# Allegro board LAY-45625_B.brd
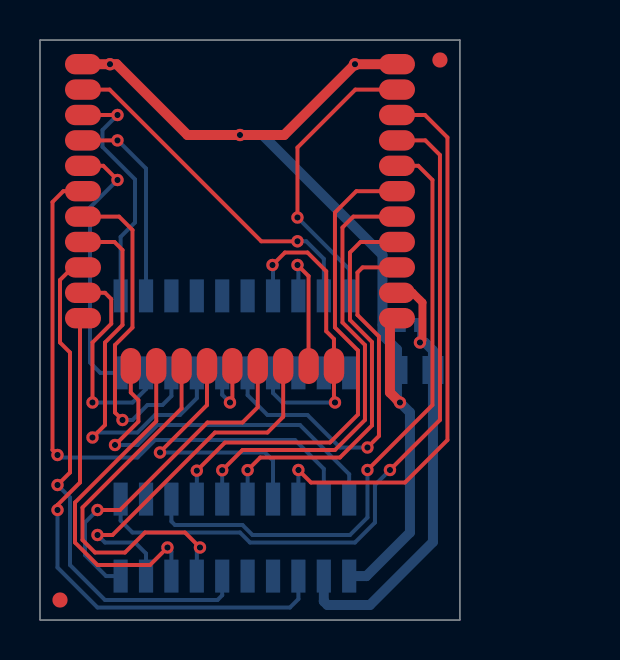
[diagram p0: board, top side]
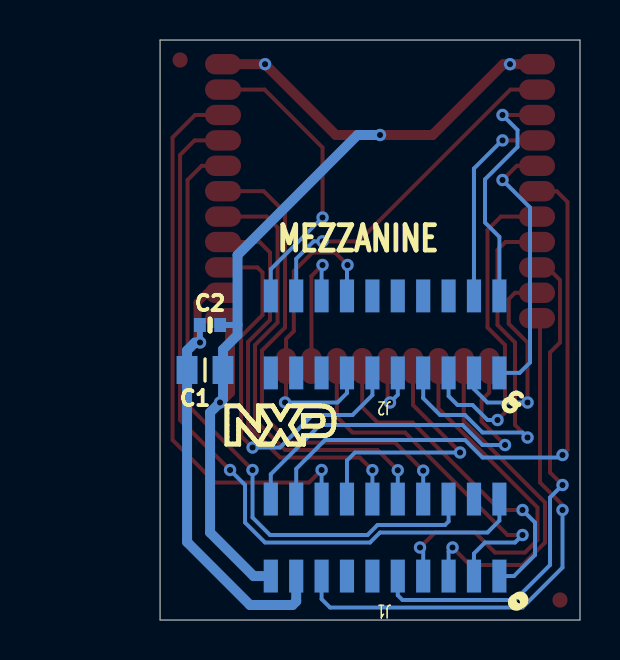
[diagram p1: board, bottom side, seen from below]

Outline 21 x 29 mm; copper layers: TOP, BOTTOM. Coordinates in mm from the lower left corner of the outline.
Outline path: 0,29 21,29 21,0 0,0 0,29

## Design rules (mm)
net group PH_SP_ALIM: nets VDD
net group PH_SP_DEFAULT: nets ANT_SEL LA LB LNA_BYPASS PIO_0/SPI1_SCK PIO_1/SPI1_MISO PIO_2/SPI1_MOSI PIO_3/SPI1_SSELN0 PIO_4/PWM4-PU PIO_5/ISP_ENTRY PIO_6/PWM6-PD PIO_7/PWM7-PD PIO_8/USART0_TXD PIO_9/USART0_RXD PIO_10/I2C0_SCL PIO_11/I2C0_SDA PIO_12/SWCLK PIO_13/SWDIO PIO_14/ADC0 PIO_15/ADC1 PIO_16/SPIFI_CSN PIO_17/SPIFI_IO3 PIO_18/SPIFI_CLK PIO_19/SPIFI_IO0 PIO_20/SPIFI_IO2 PIO_21_SPIFI_IO1 RSTN
net group PH_SP_MASSE: nets GND

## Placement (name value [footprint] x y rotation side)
1  BUBBLE01_CI  [BUBBLE_DIAM8]  27 7.56 0 top
C1  NC_22uF  [C0805]  18.75 12.5 180 bottom
C2  NC_100nF  [C0402]  18.5 14.75 180 bottom
FID1  NC  [FID1]  20 28 0 top
FID2  NC  [FID1]  1 1 0 top
J1  -  [M50-3121045]  9.75 4.12 0 bottom
J2  -  [M50-3121045]  9.75 14.28 0 bottom
LY1  NC  [SMD_LYRE_31PTS_MEZZA_JN518X]  2 25.25 0 top
NOREF  -  []  130.5 -19.5 0 top
NOREF#2  -  []  0 0 90 top
NOREF#3  -  []  0 0 0 top
NOREF#4  -  []  -74 -87 0 top
NOREF#5  -  []  -77.65 35.55 0 top
NOREF#6  -  []  15 9.75 180 bottom

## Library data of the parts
1 = BUBBLE: alternate symbols: (BUBBLE_DIAM4)
C1 = CAPA: alternate symbols: (0805C); tolerance: 20%
C2 = CAPA: User Part Number: BCNNUMBER; Tolerance: 5%; alternate symbols: (0402C); tolerance: 5%
FID1 FID2 = MIRE
J1 J2 = CON20AP
LY1 = LYRE_MODJN518x_31PTS

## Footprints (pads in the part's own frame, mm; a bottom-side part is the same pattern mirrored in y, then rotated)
BUBBLE_DIAM8
  round 0 smd: 1(0,0)
C0402
  rect 0.6x0.7 smd: 1(-0.508,0) 2(0.508,0)
C0805
  rect 1.05x1.4 smd: 1(-0.9,0) 2(0.9,0)
FID1
  round 0.76 smd: 1(0,0)
M50-3121045
  rect 0.71x1.65 smd: 1(-5.715,1.925) 2(-5.715,-1.925) 3(-4.445,1.925) 4(-4.445,-1.925) 5(-3.175,1.925) 6(-3.175,-1.925) 7(-1.905,1.925) 8(-1.905,-1.925) 9(-0.635,1.925) 10(-0.635,-1.925) 11(0.635,1.925) 12(0.635,-1.925) 13(1.905,1.925) 14(1.905,-1.925) 15(3.175,1.925) 16(3.175,-1.925) 17(4.445,1.925) 18(4.445,-1.925) 19(5.715,1.925) 20(5.715,-1.925)
SMD_LYRE_31PTS_MEZZA_JN518X
  oval 1.8x1.02 smd: 1(0,2.54) 2(0,1.27) 3(0,0) 4(0,-1.27) 5(0,-2.54) 6(0,-3.81) 7(0,-5.08) 8(0,-6.35) 9(0,-7.62) 10(0,-8.89) 11(0,-10.16) 21(16,-10.16) 22(16,-8.89) 23(16,-7.62) 24(16,-6.35) 25(16,-5.08) 26(16,-3.81) 27(16,-2.54) 28(16,-1.27) 29(16,0) 30(16,1.27) 31(16,2.54)
  oval 1.02x1.8 smd: 12(2.54,-12.7) 13(3.81,-12.7) 14(5.08,-12.7) 15(6.35,-12.7) 16(7.62,-12.7) 17(8.89,-12.7) 18(10.16,-12.7) 19(11.43,-12.7) 20(12.7,-12.7)

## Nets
GND: C1.2 C2.2 J1.19 LY1.1 LY1.21 LY1.31
VDD: C1.1 C2.1 J1.17 LY1.22(VDD)
ANT_SEL: J2.18 LY1.2
LA: J2.4 LY1.4
LB: J2.2 LY1.3
LNA_BYPASS: J2.20 LY1.30
PIO_0/SPI1_SCK: J2.1 LY1.5
PIO_1/SPI1_MISO: J1.18 LY1.6
PIO_2/SPI1_MOSI: J2.5 LY1.7
PIO_3/SPI1_SSELN0: J2.7 LY1.8
PIO_4/PWM4-PU: J1.9 LY1.9
PIO_5/ISP_ENTRY: J2.3 LY1.10
PIO_6/PWM6-PD: J1.15 LY1.11
PIO_7/PWM7-PD: J1.20 LY1.12
PIO_8/USART0_TXD: J1.5 LY1.13
PIO_9/USART0_RXD: J1.7 LY1.14
PIO_10/I2C0_SCL: J1.14 LY1.15
PIO_11/I2C0_SDA: J2.9 LY1.16
PIO_12/SWCLK: J1.1 LY1.17
PIO_13/SWDIO: J1.3 LY1.18
PIO_14/ADC0: J2.16 LY1.19
PIO_15/ADC1: J2.13 J2.14 LY1.20
PIO_16/SPIFI_CSN: J2.11 LY1.23
PIO_17/SPIFI_IO3: J1.12 LY1.24
PIO_18/SPIFI_CLK: J1.10 LY1.25
PIO_19/SPIFI_IO0: J1.8 LY1.26
PIO_20/SPIFI_IO2: J1.6 LY1.27
PIO_21_SPIFI_IO1: J1.2 LY1.28
RSTN: J1.16 LY1.29

Pads without a net: 1 1; FID1 1; FID2 1; J1 4 11 13; J2 6 8 10 12 15 17 19

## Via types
v1: diameter 0.62, hole 0.31, TOP to BOTTOM, 33 vias

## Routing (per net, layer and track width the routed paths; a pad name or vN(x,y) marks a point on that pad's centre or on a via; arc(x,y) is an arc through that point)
GND: length 52.5
  TOP w0.5: v1(18,10.88) 17.5,11.38 17.5,14.74 17.85,15.09 LY1.21 ; LY1.1 v1(3.5,27.79) 3.83,27.79 7.38,24.25 v1(10,24.25) 12.21,24.25 v1(15.75,27.79) LY1.31
  BOTTOM w0.3: 17.12,14.75 C2.2
  BOTTOM w0.5: v1(10,24.25) 11.12,24.25 17.12,18.25 17.12,14.25 17.85,13.53 C1.2 17.85,11.03 v1(18,10.88) 18.5,10.38 18.5,4.38 16.32,2.2 J1.19
VDD: length 22.7
  TOP w0.4: v1(19,13.88) 19.12,14 19.12,15.88 18.64,16.36 LY1.22
  BOTTOM w0.3: C2.1 19.01,13.88 v1(19,13.88)
  BOTTOM w0.5: v1(19,13.88) 19.25,13.88 19.65,13.47 C1.1 19.65,3.9 16.5,0.75 14.38,0.75 14.19,0.93 J1.17
ANT_SEL: length 17.5
  TOP w0.2: v1(12.88,18.93) 11.06,18.93 3.48,26.52 LY1.2
  BOTTOM w0.2: v1(12.88,18.93) 13.31,18.93 14.19,18.06 J2.18
LA: length 10.3
  TOP w0.2: LY1.4 v1(3.88,23.98)
  BOTTOM w0.2: J2.4 5.3,22.57 3.9,23.98 v1(3.88,23.98)
LB: length 12.2
  TOP w0.2: LY1.3 v1(3.88,25.25)
  BOTTOM w0.2: v1(3.88,25.25) 3.12,24.5 3.12,23.66 4.75,22.03 4.75,19.88 4.03,19.16 J2.2
LNA_BYPASS: length 14.8
  TOP w0.2: LY1.30 15.77,26.52 12.88,23.62 v1(12.88,20.12)
  BOTTOM w0.2: J2.20 15.46,17.54 v1(12.88,20.12)
PIO_0/SPI1_SCK: length 13.6
  TOP w0.2: v1(3.88,22) 3.17,22.71 LY1.5
  BOTTOM w0.2: v1(3.88,22) 2.5,20.62 2.5,12.88 3.02,12.36 J2.1
PIO_1/SPI1_MISO: length 30.2
  TOP w0.2: v1(0.88,8.25) 0.62,8.5 0.62,20.9 1.17,21.44 LY1.6
  BOTTOM w0.2: v1(0.88,8.25) 1,8.12 4.88,8.12 5.75,9 12.75,9 14.19,7.56 J1.18
PIO_2/SPI1_MOSI: length 17
  TOP w0.2: v1(4.12,10) 3.75,10.38 3.75,13.75 4.62,14.62 4.62,19.5 3.96,20.17 LY1.7
  BOTTOM w0.2: v1(4.12,10) 4.62,10 5.38,10.75 6.12,10.75 6.57,11.2 J2.5
PIO_3/SPI1_SSELN0: length 19.6
  TOP w0.2: v1(2.62,9.12) 3.25,9.75 3.25,13.88 4.12,14.75 4.12,18.5 3.73,18.9 LY1.8
  BOTTOM w0.2: J2.7 7.84,11.09 7,10.25 5.75,10.25 4.88,9.38 2.88,9.38 v1(2.62,9.12)
PIO_4/PWM4-PU: length 25.6
  TOP w0.2: LY1.9 1.63,17.63 1,17 1,13.88 1.5,13.38 1.5,7.38 v1(0.88,6.75)
  BOTTOM w0.2: v1(0.88,6.75) 1.5,6.12 1.5,2.75 3.25,1 8.88,1 9.11,1.24 J1.9
PIO_5/ISP_ENTRY: length 11
  TOP w0.2: v1(2.62,10.88) 2.62,13.88 3.56,14.81 3.56,16.05 3.25,16.36 LY1.10
  BOTTOM w0.2: J2.3 5.3,11.55 4.63,10.88 v1(2.62,10.88)
PIO_6/PWM6-PD: length 27.1
  TOP w0.2: LY1.11 2,6.88 0.88,5.75 v1(0.88,5.5)
  BOTTOM w0.2: J1.15 12.92,1.05 12.5,0.62 2.88,0.62 0.88,2.62 v1(0.88,5.5)
PIO_7/PWM7-PD: length 18.8
  TOP w0.2: LY1.12 4.54,11.38 4.92,10.99 4.92,9.92 v1(3.75,8.75)
  BOTTOM w0.2: J1.20 15.46,7.29 13,9.75 5.88,9.75 4.88,8.75 v1(3.75,8.75)
PIO_8/USART0_TXD: length 17.3
  TOP w0.2: v1(6.38,3.62) 5.5,2.75 2.88,2.75 1.75,3.88 1.75,5.88 5.81,9.94 5.81,12.55 LY1.13
  BOTTOM w0.2: v1(6.38,3.62) 6.57,3.43 J1.5
PIO_9/USART0_RXD: length 19
  TOP w0.2: v1(8,3.62) 7.25,4.38 5.25,4.38 4.25,3.38 2.75,3.38 2.12,4 2.12,5.62 7.08,10.58 LY1.14
  BOTTOM w0.2: v1(8,3.62) 7.84,3.47 J1.7
PIO_10/I2C0_SCL: length 12.9
  TOP w0.2: v1(6,8.38) 6,8.39 8.35,10.74 LY1.15
  BOTTOM w0.2: J1.14 11.65,7.97 11.25,8.38 v1(6,8.38)
PIO_11/I2C0_SDA: length 3.4
  TOP w0.2: LY1.16 9.62,10.99 v1(9.5,10.88)
  BOTTOM w0.2: v1(9.5,10.88) 9.11,11.26 J2.9
PIO_12/SWCLK: length 16.8
  TOP w0.2: v1(2.88,5.5) 4,5.5 8.38,9.88 10.12,9.88 10.89,10.64 LY1.17
  BOTTOM w0.2: v1(2.88,5.5) 2.25,4.88 2.25,3.25 3.3,2.2 J1.1
PIO_13/SWDIO: length 18.1
  TOP w0.2: v1(2.88,4.25) 3.62,4.25 8.75,9.38 11.38,9.38 12.16,10.16 LY1.18
  BOTTOM w0.2: v1(2.88,4.25) 3.25,3.88 4.75,3.88 5.3,3.32 J1.3
PIO_14/ADC0: length 7
  TOP w0.2: v1(12.88,17.75) 13.43,17.2 LY1.19
  BOTTOM w0.2: J2.16 12.92,17.7 v1(12.88,17.75)
PIO_15/ADC1: length 15.9
  TOP w0.2: v1(14.75,10.88) 14.7,10.93 LY1.20 14.7,14.05 14.31,14.44 14.31,17.44 13.38,18.38 12.25,18.38 v1(11.62,17.75)
  BOTTOM w0.2: v1(11.62,17.75) 11.65,17.72 J2.14 ; v1(14.75,10.88) 12.12,10.88 11.65,11.35 J2.13
PIO_16/SPIFI_CSN: length 19.9
  TOP w0.2: LY1.23 16.13,17.63 15.88,17.38 15.88,15.25 16.95,14.18 16.95,9.2 v1(16.38,8.62)
  BOTTOM w0.2: J2.11 10.38,11.24 11.38,10.25 13.38,10.25 15,8.62 v1(16.38,8.62)
PIO_17/SPIFI_IO3: length 20.4
  TOP w0.2: LY1.24 16.02,18.9 15.5,18.38 15.5,15 16.6,13.9 16.6,9.72 15,8.12 11.01,8.12 v1(10.38,7.49)
  BOTTOM w0.2: J1.12 v1(10.38,7.49)
PIO_18/SPIFI_CLK: length 22.8
  TOP w0.2: v1(9.11,7.49) 10.12,8.5 14.75,8.5 16.25,10 16.25,13.75 15.12,14.88 15.12,19.62 15.67,20.17 LY1.25
  BOTTOM w0.2: J1.10 v1(9.11,7.49)
PIO_19/SPIFI_IO0: length 24.9
  TOP w0.2: LY1.26 15.81,21.44 14.75,20.38 14.75,14.62 15.9,13.47 15.9,10.28 14.5,8.88 9.25,8.88 v1(7.84,7.47)
  BOTTOM w0.2: J1.8 v1(7.84,7.47)
PIO_20/SPIFI_IO2: length 31.7
  TOP w0.2: v1(16.38,7.5) 19.62,10.75 19.62,22 18.91,22.71 LY1.27
  BOTTOM w0.2: J1.6 6.57,4.93 6.75,4.75 10.12,4.75 10.62,4.25 15.5,4.25 16.38,5.12 v1(16.38,7.5)
PIO_21_SPIFI_IO1: length 36.7
  TOP w0.2: LY1.28 19.27,23.98 20,23.25 20,10 v1(17.5,7.5)
  BOTTOM w0.2: v1(17.5,7.5) 16.75,6.75 16.75,4.88 15.75,3.88 10.5,3.88 10,4.38 4.62,4.38 4.03,4.97 J1.2
RSTN: length 28
  TOP w0.2: LY1.29 19.25,25.25 20.38,24.12 20.38,9 18.25,6.88 13.55,6.88 v1(12.92,7.5)
  BOTTOM w0.2: v1(12.92,7.5) J1.16

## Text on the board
Ref Des/Assembly Bottom: BOTTOM
Ref Des/Silkscreen Bottom: MEZZANINE
Ref Des/Assembly Top: TOP
MARQUAGE_COMMUN: B
User.6: PCB2410-2 OM15026-1 JN5179 MEZZANINE 06/10/2015 | MILLING 313 00
User.25: INT3 311 00 | LAYER 3
User.26: INT2 311 00 | LAYER 2
User.45: 1 | CN2 | CN1 | M2 | M1 | R10 | R15 | R14 | R12 | R13 | R11 | R9 | R7 | R2 | R8 | R5 | R3 | M5 | IC10 | IC11 | IC12 | D1 | IC7 | IC8 | IC9 | D2 | K | R16 | IC5 | IC1 | IC4 | IC3 | IC6 | IC2 | R17 | D3 | D13 | C1 | RG1 | D5 | R50 | R51 | R52 | R24 | C2 | D4 | R25 | IC17 | IC18 | IC19 | SP1 | D6 | C8 | C6 | IC13 | J4 | IC16 | C7 | ANT1 | TP4 | TP3 | JP2 | C14 | R36 | SW1 | TP2 | TP1 | IC15 | D9 | R40 | D8 | CN4 | CN3 | J2 | J1 | M3 | SP2 | R42 | SP4 | C10 | C15 | ST1 | SP5 | R43 | SP3 | SP6 | ST2 | C16 | SP7 | J5 | C13 | M6 | SP8 | JP4 | JP3 | SP10 | JP5 | SP9 | SW2 | SP11 | SP12 | M4 | JP6 | 2 | 3 | IC14 | J6 | R4 | R6 | C5 | C4 | C3 | R1 | R22 | R21 | R20 | R19 | R18 | R23 | J3 | R49 | C19 | R29 | R28 | R26 | R27 | R35 | R34 | R33 | R32 | R31 | R30 | R37 | D7 | R38 | C9 | FE1 | R39 | R41 | C17 | C11 | Y1 | C12 | R44 | R45 | D12 | D11 | D10 | C18 | R48 | R47 | R46 | JP1 | LAY-45625_B | PCB2445-1 | PCB2446-1 | PCB2447-1 | PCB2448-1 | OM15064-1 PCB2445-1 | OM15065-1 PCB2446-1 | OM15067-1 PCB2447-1 | OM15068-1 PCB2448-1 | BOARD ORIENTATION | All rights are reserved. Reproduction in | whole or in part is prohibited without | the written consent of the copyright owner | OM15064-1 | OM15065-1 | OM15067-1 | OM15068-1 | OM15077 | NXP Semiconductors | 6501 William Cannon Drive West | Austin, TX 78735-8598 | Date | Draw by | Verify | Modifications | SIZE | IND. | Date : 08-Nov-2019 | Draw by : ASCO-SR | Checked by: V.FILLATRE | Project : OM15077 | ASSEMBLY DRAWING TOP/BOTTOM | MEZZANINE - OM15077 | DRILLING/MILLING | Protection: SOLDERMASK(BLUE) | Finition : Ni/AU CHEMICAL | Material : ... | File. | TOP/BOTTOM | Marging : +/-0.1 | Manufact.level : 5 | Scale : 1/1 | Nbr of layers : 2 | Silkscreen(WHITE) | TOP   : NO | BOTTOM: YES | REV. | PL. | FR4,16/10mm | COLOR | JN5179 MEZZANINE 19/04/2016 | JN518X MEZZANINE | PCB2457-1.0_OM15077-1 | PCB2444-1.0 OM15063-1 | BLUE | FIGURE | DIAMETRE / HOLESIZE | 0,30 mm (PERCE) | LEGENDE DE PERCAGE / DRILL LEGEND | ALL UNITS ARE IN MILLIMETERS | PLATED | Qte / Qty | 33 | MILLING | D | C | A4 | LAY-45625 | B | A | 4 | (TOP)
